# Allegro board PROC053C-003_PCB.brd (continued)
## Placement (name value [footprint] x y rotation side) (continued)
R468  DNI  [SM-7351-RES-0402]  106.68 108.92 270 bottom
R472  0  [SM-7351-RES-0603]  171.12 80.01 0 bottom
R473  0  [SM-7351-RES-0402]  156.46 73.53 0 bottom
R474  0  [SM-7351-RES-0402]  155.63 76.33 0 top
R475  0  [SM-7351-RES-0402]  159.56 71.51 90 top
R476  0  [SM-7351-RES-0402]  162.74 68.97 90 top
R477  0  [SM-7351-RES-0402]  163.63 71.51 90 top
R478  0  [SM-7351-RES-0402]  164.9 71.51 90 top
R479  12K  [SM-7351-RES-0402]  156.01 81.41 180 top
R480  0  [SM-7351-RES-0402]  160.71 71.51 90 top
R481  0  [SM-7351-RES-0402]  161.59 68.97 90 top
R482  0  [SM-7351-RES-0402]  165.91 71.51 90 top
R483  0  [SM-7351-RES-0402]  166.93 71.51 90 top
R484  4.7K  [SM-7351-RES-0402]  164.9 69.09 90 top
R485  10K  [SM-7351-RES-0402]  155.63 77.35 180 top
R486  0  [SM-7351-RES-0402]  113.03 62.74 270 top
R487  0  [SM-7351-RES-0402]  111.89 62.74 270 top
R489  0  [SM-7351-RES-0402]  169.09 71.51 90 top
R491  4.7K  [SM-7351-RES-0402]  163.12 88.78 90 top
R492  0  [SM-7351-RES-0402]  165.28 88.78 270 top
R493  220  [SM-7351-RES-0402]  161.98 88.78 90 top
R494  10K  [SM-7351-RES-0402]  164.13 88.78 270 top
R495  2.2K  [SM-7351-RES-0402]  162.61 85.98 270 bottom
R496  10K  [SM-7351-RES-0402]  163.63 85.98 90 bottom
R497  0  [SM-7351-RES-0402]  79.38 87.46 180 top
R498  DNI  [SM-7351-RES-0402]  61.21 64.14 270 bottom
R499  0  [SM-7351-RES-0402]  71.66 77.75 0 top
R500  DNI  [SM-7351-RES-0402]  62.36 64.14 270 bottom
R502  33  [SM-7351-RES-0402]  171.7 21.29 180 bottom
R503  120  [SM-7351-RES-0402]  155.58 11.13 90 bottom
R504  33  [SM-7351-RES-0402]  172.85 18.75 180 bottom
R505  49.9K  [SM-7351-RES-0402]  86.87 129.24 180 top
R506  49.9K  [SM-7351-RES-0402]  86.87 126.45 180 top
R507  49.9K  [SM-7351-RES-0402]  86.87 125.3 180 top
R508  49.9K  [SM-7351-RES-0402]  89.53 131.91 90 top
R509  49.9K  [SM-7351-RES-0402]  88.39 131.91 90 top
R510  49.9K  [SM-7351-RES-0402]  86.87 128.1 180 top
R511  49.9K  [SM-7351-RES-0402]  86.87 123.65 180 top
R512  49.9K  [SM-7351-RES-0402]  86.87 122.51 180 top
R513  49.9K  [SM-7351-RES-0402]  95.25 104.98 270 bottom
R514  0  [SM-7351-RES-0402]  16.13 13.92 180 bottom
R515  100K  [SM-7351-RES-0402]  16.13 16.21 0 bottom
R539  10K  [SM-7351-RES-0402]  53.72 38.23 270 top
R542  10K  [SM-7351-RES-0402]  49.53 38.23 270 top
R543  10K  [SM-7351-RES-0402]  50.67 38.23 270 top
R544  10K  [SM-7351-RES-0402]  52.58 38.23 270 top
R545  10K  [SM-7351-RES-0402]  54.86 38.23 90 top
R546  10K  [SM-7351-RES-0402]  33.91 34.63 0 bottom
R547  DNI  [SM-7351-RES-0402]  21.84 42.88 0 bottom
R548  10K  [SM-7351-RES-0402]  29.46 31.58 270 bottom
R549  10K  [SM-7351-RES-0402]  30.48 31.58 270 bottom
R550  0  [SM-7351-RES-0402]  30.73 31.58 270 top
R551  10K  [SM-7351-RES-0402]  23.88 14.22 180 bottom
R553  10K  [SM-7351-RES-0402]  24.38 3.17 270 bottom
R554  0  [SM-7351-RES-0402]  174.12 75.01 270 top
R555  0  [SM-7351-RES-0402]  175.13 75.01 270 top
R556  DNI  [SM-7351-RES-0402]  124.08 64.47 0 top
R557  DNI  [SM-7351-RES-0402]  85.47 90.51 0 top
R558  0  [SM-7351-RES-0402]  65.15 22.86 180 top
R559  0  [SM-7351-RES-0402]  65.15 23.88 0 top
R560  DNI  [SM-7351-RES-0402]  58.8 12.45 90 top
R561  DNI  [SM-7351-RES-0402]  56.52 12.45 270 top
R562  DNI  [SM-7351-RES-0402]  57.66 12.45 90 top
R563  DNI  [SM-7351-RES-0402]  127.89 66.88 0 top
R564  0  [SM-7351-RES-0402]  120.27 85.81 0 top
R565  0  [SM-7351-RES-0402]  127.89 86.82 180 top
R566  0  [SM-7351-RES-0402]  157.23 98.63 0 bottom
R567  0  [SM-7351-RES-0402]  157.23 97.62 0 bottom
R568  0  [SM-7351-RES-0402]  28.45 31.58 270 bottom
R569  0  [SM-7351-RES-0402]  81.91 84.28 180 bottom
R570  10K  [SM-7351-RES-0402]  143.51 130.76 0 bottom
R571  10K  [SM-7351-RES-0402]  147.83 114.76 270 top
R572  0  [SM-7351-RES-0402]  131.44 114.76 90 top
R573  0  [SM-7351-RES-0402]  106.68 8.25 270 top
R574  0  [SM-7351-RES-0402]  112.9 99.78 270 bottom
R575  0  [SM-7351-RES-0402]  112.9 103.84 270 top
R576  0  [SM-7351-RES-0402]  106.81 105.66 90 top
R577  100K  [SM-7351-RES-0402]  114.43 8.89 180 top
R578  100K  [SM-7351-RES-0402]  114.43 7.62 0 top
R579  2.2K  [SM-7351-RES-0402]  130.18 10.16 180 top
R580  100  [SM-7351-RES-0402]  60.2 37.21 0 top
R581  100  [SM-7351-RES-0402]  78.61 77.17 90 top
R582  0  [SM-7351-RES-0402]  120.27 65.99 180 top
R583  0  [SM-7351-RES-0402]  110.74 62.74 90 top
R584  0  [SM-7351-RES-0402]  92.46 102.19 270 top
R585  0  [SM-7351-RES-0402]  157.23 96.6 0 bottom
R586  0  [SM-7351-RES-0402]  143.76 96.22 180 bottom
R587  0  [SM-7351-RES-0402]  181.89 93.68 0 bottom
R588  0  [SM-7351-RES-0402]  132.72 114.68 90 bottom
R589  220  [SM-7351-RES-0402]  9.53 18.16 180 bottom
R590  0  [SM-7351-RES-0402]  9.53 17.1 0 bottom
R591  100K  [SM-7351-RES-0402]  9.53 16.08 0 bottom
R592  100K  [SM-7351-RES-0402]  16.13 19.64 0 bottom
R593  0  [SM-7351-RES-0402]  16.13 20.66 0 bottom
R594  0  [SM-7351-RES-0402]  9.53 20.53 0 bottom
R595  100K  [SM-7351-RES-0402]  9.53 19.51 0 bottom
R596  220  [SM-7351-RES-0402]  9.53 14.86 180 bottom
R597  100K  [SM-7351-RES-0402]  16.13 12.91 0 bottom
R598  0  [SM-7351-RES-0402]  16.13 17.23 0 bottom
R599  100K  [SM-7351-RES-0402]  9.53 12.78 0 bottom
R600  0  [SM-7351-RES-0402]  9.53 13.8 180 bottom
R601  220  [SM-7351-RES-0402]  9.53 21.59 180 bottom
R602  220  [SM-7351-RES-0402]  16.13 18.29 180 bottom
R603  220  [SM-7351-RES-0402]  16.13 21.72 180 bottom
R604  220  [SM-7351-RES-0402]  16.13 14.99 180 bottom
R605  0  [SM-7351-RES-0402]  127.89 94.57 180 top
R606  0  [SM-7351-RES-0402]  127.89 95.59 180 top
R607  0  [SM-7351-RES-0402]  131.44 101.17 0 top
R608  0  [SM-7351-RES-0402]  131.44 85.55 0 top
R609  0  [SM-7351-RES-0402]  131.44 88.98 0 top
R610  0  [SM-7351-RES-0402]  131.44 102.44 0 top
R611  0  [SM-7351-RES-0402]  131.44 98.13 0 top
R612  0  [SM-7351-RES-0402]  131.44 103.71 0 top
R613  0  [SM-7351-RES-0402]  127.89 92.2 0 top
R614  0  [SM-7351-RES-0402]  127.89 89.36 0 top
R615  0  [SM-7351-RES-0402]  131.44 92.79 0 top
R616  0  [SM-7351-RES-0402]  131.44 96.22 0 top
R617  0  [SM-7351-RES-0402]  124.08 96.35 0 top
R618  0  [SM-7351-RES-0402]  131.44 94.95 0 top
R619  0  [SM-7351-RES-0402]  131.44 99.4 0 top
R620  0  [SM-7351-RES-0402]  131.44 91.52 0 top
R621  0  [SM-7351-RES-0402]  124.08 95.08 0 top
R622  0  [SM-7351-RES-0402]  124.08 92.54 0 top
R623  0  [SM-7351-RES-0402]  124.08 91.27 0 top
R624  0  [SM-7351-RES-0402]  124.08 93.81 0 top
R625  0  [SM-7351-RES-0402]  131.44 86.82 0 top
R626  0  [SM-7351-RES-0402]  124.08 87.46 0 top
R627  0  [SM-7351-RES-0402]  124.08 88.73 0 top
R628  0  [SM-7351-RES-0402]  124.08 90 0 top
R630  100  [SM-7351-RES-0402]  78.61 122.13 270 bottom
R631  100  [SM-7351-RES-0402]  77.34 120.6 270 bottom
R632  100  [SM-7351-RES-0402]  77.34 123.65 90 bottom
R633  100  [SM-7351-RES-0402]  78.61 119.08 90 bottom
R634  0  [SM-7351-RES-0402]  120.27 87.08 180 top
R635  0  [SM-7351-RES-0402]  127.89 88.09 180 top
R636  0  [SM-7351-RES-0402]  124.08 86.31 180 top
R637  10K  [SM-7351-RES-0402]  157.23 99.65 180 bottom
R638  0  [SM-7351-RES-0402]  165.74 5.03 180 top
R639  0.05ohm  [SM_RES_LVK12]  64.26 75.39 90 top
R640  0.05ohm  [SM_RES_LVK12]  105.28 134.83 180 top
R641  0.01ohm  [SM_RES_LVK12]  112.65 134.7 180 top
R642  0.02ohm  [SM_RES_LVK12]  120.78 134.7 180 top
R643  0  [SM-7351-RES-0402]  74.93 73.66 0 top
R644  10K  [SM-7351-RES-0402]  86.61 107.4 90 top
R645  10K  [SM-7351-RES-0402]  93.85 103.25 90 top
R646  51K OHM  [RC0402]  157.39 117.9 90 top
R647  158K OHM  [RC0402]  161.07 121.58 90 top
R648  18.2K  [SM-7351-RES-0402]  161.07 119.42 90 top
R649  10K  [SM-7351-RES-0402]  45.59 38.23 90 top
R650  100  [SM-7351-RES-0402]  44.58 38.23 270 top
R652  0  [SM-7351-RES-0402]  50.29 24.64 270 top
R653  0  [SM-7351-RES-0402]  51.31 24.64 270 top
R654  10K  [SM-7351-RES-0402]  56.01 24.64 270 top
R655  100  [SM-7351-RES-0402]  54.99 24.64 90 top
R656  0  [SM-7351-RES-0603]  151.13 120.22 0 top
R657  0  [SM-7351-RES-0402]  137.01 128.34 0 bottom
R658  0  [SM-7351-RES-0402]  138.81 134.7 270 bottom
R659  0  [SM-7351-RES-0402]  85.47 89.49 0 top
R660  0  [SM-7351-RES-0402]  92.84 98.25 270 top
R661  0  [SM-7351-RES-0402]  119.63 74.25 180 bottom
R662  0  [SM-7351-RES-0402]  120.27 80.85 180 top
R663  0  [SM-7351-RES-0402]  105.54 113.37 270 top
R664  0  [SM-7351-RES-0402]  108.58 99.78 270 bottom
R665  0  [SM-7351-RES-0402]  104.52 113.37 270 top
R666  0  [SM-7351-RES-0402]  119.63 73.23 180 bottom
R669  0  [SM-7351-RES-0402]  113.54 99.78 90 top
R670  0  [SM-7351-RES-0402]  112.27 99.78 90 top
R671  0  [SM-7351-RES-0402]  111.38 99.78 90 bottom
R672  0  [SM-7351-RES-0402]  111.63 103.84 90 top
R673  0  [SM-7351-RES-0402]  127.89 85.81 180 top
R674  0  [SM-7351-RES-0402]  120.27 79.08 0 bottom
R675  0  [SM-7351-RES-0402]  127.89 83.27 180 top
R676  0  [SM-7351-RES-0402]  127.89 84.54 180 top
R677  0  [SM-7351-RES-0402]  179.1 80.73 180 bottom
R678  0  [SM-7351-RES-0402]  70.99 117.18 180 bottom
R679  0  [SM-7351-RES-0402]  158.78 117.9 270 top
R680  10K  [SM-7351-RES-0402]  73.53 114.89 270 bottom
R681  19.6K  [SM-7351-RES-0402]  73.53 112.86 90 bottom
R682  0  [SM-7351-RES-0402]  68.45 23.75 90 top
R683  0  [SM-7351-RES-0402]  69.47 23.75 90 top
R684  0  [SM-7351-RES-0402]  120.27 67.01 0 top
R685  0  [SM-7351-RES-0402]  124.08 68.28 180 top
R686  0  [SM-7351-RES-0402]  100.84 99.78 270 top
R687  100  [SM-7351-RES-0402]  77.34 117.68 90 bottom
R688  0  [SM-7351-RES-0402]  103.38 99.78 270 top
R689  0  [SM-7351-RES-0402]  104.27 121.75 270 top
R690  0  [SM-7351-RES-0402]  104.65 99.78 270 top
R691  0  [SM-7351-RES-0402]  105.92 99.78 270 top
R692  0  [SM-7351-RES-0402]  103.89 102.44 270 top
R693  220  [SM-7351-RES-0402]  72.64 105.54 180 bottom
R694  0  [SM-7351-RES-0402]  81.03 100.28 90 bottom
R695  100K  [SM-7351-RES-0402]  79.76 100.28 90 bottom
R696  220  [SM-7351-RES-0402]  76.07 105.54 180 bottom
R697  100K  [SM-7351-RES-0402]  76.45 100.28 90 bottom
R698  0  [SM-7351-RES-0402]  77.47 100.28 270 bottom
R699  220  [SM-7351-RES-0402]  79.5 105.54 180 bottom
R700  100K  [SM-7351-RES-0402]  72.9 100.28 90 bottom
R701  0  [SM-7351-RES-0402]  74.04 100.28 90 bottom
R702  220  [SM-7351-RES-0402]  68.83 103.5 180 bottom
R703  0  [SM-7351-RES-0402]  70.74 91.14 90 bottom
R704  100K  [SM-7351-RES-0402]  69.6 91.14 90 bottom
R705  220  [SM-7351-RES-0402]  69.22 89.41 180 bottom
R706  100K  [SM-7351-RES-0402]  69.47 84.03 90 bottom
R707  0  [SM-7351-RES-0402]  70.61 84.03 270 bottom
R708  220  [SM-7351-RES-0402]  67.18 95.12 180 bottom
R709  100K  [SM-7351-RES-0402]  69.09 98.25 90 bottom
R710  0  [SM-7351-RES-0402]  70.23 98.25 90 bottom
R711  DNI  [SM-7351-RES-0402]  132.46 101.17 180 top
R712  DNI  [SM-7351-RES-0402]  132.46 96.22 180 top
R713  DNI  [SM-7351-RES-0402]  125.09 93.81 180 top
R714  DNI  [SM-7351-RES-0402]  132.46 85.55 180 top
R715  DNI  [SM-7351-RES-0402]  132.46 88.98 180 top
R716  DNI  [SM-7351-RES-0402]  132.46 102.44 180 top
R717  DNI  [SM-7351-RES-0402]  132.46 103.71 180 top
R718  DNI  [SM-7351-RES-0402]  132.46 98.13 180 top
R719  DNI  [SM-7351-RES-0402]  132.46 92.79 180 top
R720  DNI  [SM-7351-RES-0402]  125.09 96.35 180 top
R721  DNI  [SM-7351-RES-0402]  132.46 99.4 180 top
R722  DNI  [SM-7351-RES-0402]  132.46 91.52 180 top
R723  DNI  [SM-7351-RES-0402]  132.46 94.95 180 top
R724  DNI  [SM-7351-RES-0402]  125.09 91.27 180 top
R725  DNI  [SM-7351-RES-0402]  132.46 86.82 180 top
R726  DNI  [SM-7351-RES-0402]  125.09 88.73 180 top
R727  DNI  [SM-7351-RES-0402]  125.09 90 180 top
R728  DNI  [SM-7351-RES-0402]  125.09 87.46 180 top
R729  100  [SM-7351-RES-0402]  161.54 7.96 90 top
R730  100  [SM-7351-RES-0402]  182.02 97.62 180 bottom
R731  100  [SM-7351-RES-0402]  184.68 95.2 90 bottom
R732  0  [SM-7351-RES-0402]  106.93 99.78 270 top
R733  0  [SM-7351-RES-0402]  106.05 102.44 270 top
R734  0  [SM-7351-RES-0402]  105.03 102.44 270 top
R735  0  [SM-7351-RES-0402]  107.06 102.44 90 top
R736  0  [SM-7351-RES-0402]  82.68 92.46 180 top
R737  0  [SM-7351-RES-0402]  82.68 91.44 180 top
R738  0  [SM-7351-RES-0402]  85.47 88.39 180 top
R739  0  [SM-7351-RES-0402]  131.06 59.31 270 top
R740  0  [SM-7351-RES-0402]  132.21 59.31 270 top
R741  10K  [SM-7351-RES-0402]  95 135.84 90 bottom
R742  0  [SM-7351-RES-0603]  140.34 126.07 270 bottom
R743  0  [SM-7351-RES-0402]  103.38 143.72 270 top
R744  0  [SM-7351-RES-0402]  120.9 99.9 270 top
R746  DNI  [SM-7351-RES-0402]  114.55 99.9 270 bottom
R747  DNI  [SM-7351-RES-0402]  118.36 97.74 90 bottom
R748  DNI  [SM-7351-RES-0402]  30.61 93.17 90 top
R749  DNI  [SM-7351-RES-0402]  119.51 101.17 90 bottom
R750  DNI  [SM-7351-RES-0402]  118.24 101.17 90 bottom
R751  DNI  [SM-7351-RES-0402]  114.55 101.94 90 bottom
R752  DNI  [SM-7351-RES-0402]  59.56 107.52 90 top
R753  DNI  [SM-7351-RES-0402]  52.58 107.52 90 top
R754  240  [SM-7351-RES-0402]  143.13 40.47 90 bottom
R755  240  [SM-7351-RES-0402]  143.13 55.71 90 bottom
R756  47  [SM-7351-RES-0402]  151 59.14 180 top
R757  47  [SM-7351-RES-0402]  144.02 70.95 270 bottom
R758  47  [SM-7351-RES-0402]  143 70.95 270 top
R759  47  [SM-7351-RES-0402]  151 66.25 180 top
R760  47  [SM-7351-RES-0402]  151 67.26 180 top
R761  47  [SM-7351-RES-0402]  151 65.23 180 top
R762  47  [SM-7351-RES-0402]  151 64.22 180 bottom
R763  47  [SM-7351-RES-0402]  151 61.17 180 top
R764  47  [SM-7351-RES-0402]  151 60.15 180 top
R765  47  [SM-7351-RES-0402]  146.05 70.95 270 bottom
R766  47  [SM-7351-RES-0402]  147.07 70.95 270 bottom
R767  47  [SM-7351-RES-0402]  148.08 70.95 270 bottom
R768  47  [SM-7351-RES-0402]  151 60.15 180 bottom
R769  47  [SM-7351-RES-0402]  151 66.25 180 bottom
R770  47  [SM-7351-RES-0402]  151 61.17 180 bottom
R771  47  [SM-7351-RES-0402]  151 62.18 180 top
R772  47  [SM-7351-RES-0402]  151 63.2 180 top
R773  47  [SM-7351-RES-0402]  151 63.2 180 bottom
R774  47  [SM-7351-RES-0402]  151 62.18 180 bottom
R775  47  [SM-7351-RES-0402]  151 65.23 180 bottom
R776  47  [SM-7351-RES-0402]  151 59.14 180 bottom
R777  47  [SM-7351-RES-0402]  145.03 70.95 270 bottom
R778  47  [SM-7351-RES-0402]  143 70.95 270 bottom
R779  47  [SM-7351-RES-0402]  151 64.22 180 top
R780  49.9  [SM-7351-RES-0402]  140.97 70.95 270 top
R781  49.9  [SM-7351-RES-0402]  141.99 70.95 270 top
R782  100K  [SM-7351-RES-0402]  163.45 57.1 0 bottom
R783  0  [SM-7351-RES-0402]  163.07 59.01 90 bottom
R784  10  [SM-7351-RES-0402]  157.23 60.66 90 bottom
R785  10K  [SM-7351-RES-0402]  160.66 54.18 90 bottom
R786  10K  [SM-7351-RES-0402]  159.51 54.18 270 bottom
R787  DNI  [SM-7351-RES-0402]  82.93 88.27 0 top
R788  100  [SM-7351-RES-0402]  8.76 44.32 0 bottom
R790  10K  [SM-7351-RES-0402]  16.89 42.88 90 top
R791  10K  [SM-7351-RES-0402]  18.41 46.82 180 top
R792  0  [SM-7351-RES-0402]  56.61 86.08 0 bottom
R793  20.5K  [SM-7351-RES-0402]  124.59 43.9 0 top
R794  0  [SM-7351-RES-0402]  140.69 122.38 270 bottom
R795  0  [SM-7351-RES-0402]  68.33 20.4 90 bottom
R796  0  [SM-7351-RES-0402]  65.66 23.07 90 bottom
R797  0  [SM-7351-RES-0402]  120.27 80.73 180 bottom
R798  10K  [SM-7351-RES-0402]  165.74 3.89 0 top
R799  10K  [SM-7351-RES-0402]  100.33 124.16 90 top
R800  10K  [SM-7351-RES-0402]  85.47 93.34 180 top
R801  0.05ohm  [SM_RES_LVK12]  65.53 53.8 0 top
R802  0  [SM-7351-RES-0402]  85.47 95.38 180 top
R803  0  [SM-7351-RES-0402]  85.47 91.52 180 top
R804  DNI  [SM-7351-RES-0402]  130.68 68.79 0 top
R805  DNI  [SM-7351-RES-0402]  130.68 70.31 0 top
R806  47  [SM-7351-RES-0402]  124.08 27.56 180 bottom
R807  47  [SM-7351-RES-0402]  144.91 55.71 90 bottom
R808  10K  [SM-7351-RES-0402]  8.76 43.18 0 bottom
R809  0  [SM-7351-RES-0402]  93.98 98.3 270 top
R810  10K  [SM-7351-RES-0402]  146.3 138.43 90 top
R811  10K  [SM-7351-RES-0402]  151.05 142.53 180 top
R812  1M  [SM-7351-RES-0402]  30.23 18.41 180 bottom
R813  1M  [SM-7351-RES-0402]  5.46 31.5 0 top
R814  10K  [SM-7351-RES-0402]  138.3 113.03 90 bottom
R854  0  [SM-7351-RES-0402]  145.67 125.98 270 bottom
R861  0  [SM-7351-RES-0402]  129.92 143 270 top
R862  0  [SM-7351-RES-0402]  133.22 143 270 top
R863  0  [SM-7351-RES-0402]  135.26 143 270 top
R864  0  [SM-7351-RES-0402]  137.29 143 270 top
R894  499  [SM-7351-RES-0402]  36.07 96.65 90 bottom
R895  10K  [SM-7351-RES-0402]  35.43 94.61 180 bottom
R896  DNI  [SM-7351-RES-0402]  34.92 96.65 90 bottom
R897  24.3K  [SM-7351-RES-0402]  38.1 91.31 180 bottom
R898  499  [SM-7351-RES-0402]  113.92 125.48 180 bottom
R899  10K  [SM-7351-RES-0402]  115.95 124.84 270 bottom
R900  DNI  [SM-7351-RES-0402]  113.92 124.33 180 bottom
R901  24.3K  [SM-7351-RES-0402]  119.25 127.51 270 bottom
R902  10K  [SM-7351-RES-0402]  164.85 149.1 270 bottom
R903  22.1  [SM-7351-RES-0402]  172.97 143 180 bottom
R905  DNI  [SM-7351-RES-0402]  163.83 146.56 180 bottom
R906  DNI  [SM-7351-RES-0402]  136.27 98.81 180 top
R907  DNI  [SM-7351-RES-0402]  137.03 90.93 180 top
R908  DNI  [SM-7351-RES-0402]  128.91 98.17 0 top
R909  DNI  [SM-7351-RES-0402]  127.89 91.19 0 top
R910  DNI  [SM-7351-RES-0402]  136.27 101.85 180 top
R911  DNI  [SM-7351-RES-0402]  129.29 103.76 0 top
R912  10K  [SM-7351-RES-0402]  124.08 25.02 180 top
R913  10K  [SM-7351-RES-0402]  149.61 70.48 180 top
R914  10K  [SM-7351-RES-0402]  165.99 52.45 180 bottom
R915  DNI  [SM-7351-RES-0402]  157.61 42.04 0 bottom
R916  100  [SM-7351-RES-0402]  170.05 42.93 0 bottom
R917  10K  [SM-7351-RES-0402]  166.24 46.1 90 bottom
R918  DNI  [SM-7351-RES-0402]  157.61 44.96 0 bottom
R919  DNI  [SM-7351-RES-0402]  157.61 46.74 0 bottom
R920  0  [SM-7351-RES-0402]  157.61 47.75 0 bottom
R921  0  [SM-7351-RES-0402]  157.61 41.02 0 bottom
R922  0  [SM-7351-RES-0402]  157.61 43.94 0 bottom
R923  0  [SM-7351-RES-0402]  66.93 79.63 180 top
R924  0  [SM-7351-RES-0402]  74.93 74.68 180 top
R925  0  [SM-7351-RES-0402]  66.93 81.41 180 top
R926  0  [SM-7351-RES-0402]  63.5 64.14 270 bottom
R927  DNI  [SM-7351-RES-0402]  79.88 89.15 270 top
R928  DNI  [SM-7351-RES-0402]  96.01 103.25 90 top
R929  DNI  [SM-7351-RES-0402]  95 103.25 270 top
R930  DNI  [SM-7351-RES-0402]  80.9 86.49 0 bottom
R931  0  [SM-7351-RES-0402]  80.9 85.34 0 bottom
R932  DNI  [SM-7351-RES-0402]  95 97.66 270 bottom
R933  0  [SM-7351-RES-0402]  92.08 97.66 270 bottom
R934  DNI  [SM-7351-RES-0402]  139.17 122.3 0 bottom
R935  0 OHM  [RC0402]  55.91 77.08 180 top
R938  1K OHM  [RC0402]  51.69 56.52 90 top
R939  10K  [SM-7351-RES-0402]  52.41 69.99 90 top
R940  0 OHM  [RC0402]  49.56 69.99 270 top
R941  10K  [SM-7351-RES-0402]  50.88 61.31 270 top
R942  10K  [SM-7351-RES-0402]  49.48 61.31 90 top
R943  DNI  [SM-7351-RES-0402]  47.03 61.02 270 top
R945  10K  [SM-7351-RES-0402]  45.38 61.38 0 top
R946  DNI  [SM-7351-RES-0402]  43.6 61.02 90 top
R947  10K  [SM-7351-RES-0402]  43.92 69.71 90 top
R948  10K  [SM-7351-RES-0402]  55.91 69.16 180 top
R950  DNI  [RC0402]  116.35 144.11 90 top
R951  DNI  [RC0402]  118.35 144.11 90 top
R952  DNI  [RC0402]  151.08 144.91 0 top
R953  DNI  [RC0402]  154.35 144.34 90 top
R954  10K  [SM-7351-RES-0402]  59.23 45.55 90 top
R955  10K  [SM-7351-RES-0402]  60.29 42.84 180 top
R956  DNI  [SM-7351-RES-0402]  7.7 105.74 270 bottom
R957  0  [SM-7351-RES-0402]  5.21 53.97 90 bottom
R958  DNI  [SM-7351-RES-0402]  5.21 56.6 90 bottom
R959  0 OHM  [RC0402]  47.37 56.52 90 top
R960  DNI  [RC0402]  45.95 56.52 90 top
R961  0 OHM  [RC0402]  44.48 56.52 90 top
R964  DNI  [RC0402]  45.44 69.71 90 top
R965  0 OHM  [RC0402]  50.22 56.52 90 top
R966  0 OHM  [RC0402]  48.79 56.52 90 top
R967  0 OHM  [RC0402]  51.07 69.99 90 top
R968  0 OHM  [RC0402]  55.94 75.86 180 top
R969  0 OHM  [RC0402]  55.94 74.26 180 top
R970  0 OHM  [RC0402]  55.91 72.59 180 top
R971  0 OHM  [RC0402]  55.66 78.68 180 top
R972  0 OHM  [RC0402]  55.66 80.13 180 top
R973  0 OHM  [RC0402]  55.91 70.92 180 top
R974  0 OHM  [RC0402]  44.23 72.25 0 top
R975  0 OHM  [RC0402]  44.23 73.78 0 top
R976  0 OHM  [RC0402]  44.23 75.3 0 top
R977  0 OHM  [RC0402]  44.23 76.83 0 top
R978  0 OHM  [RC0402]  44.23 78.35 0 top
R979  0 OHM  [RC0402]  44.23 79.87 0 top
R980  DNI  [RC0402]  46.77 69.71 90 top
R981  10K  [SM-7351-RES-0402]  148.93 140.95 90 top
R982  47K  [SM-7351-RES-0402]  155.26 140.82 0 top
R983  DNI  [SM-7351-RES-0402]  144.36 129.12 90 bottom
SCKT1  DNI  [SCK-SG-BGA-6334]  102.23 81.99 270 top
SW1  B3SL  [SW_B3SL-1022P]  166.88 44.15 180 top
SW2  B3SL  [SW_B3SL-1022P]  166.88 53.42 180 top
SW3  B3SL  [SW_B3SL-1022P]  166.88 62.44 180 top
TP1  TP  [TH_TP_5002]  175.92 129.88 0 top
TP1_1  TP  [TH_TP_5002]  177.72 14 90 top
TP2  TP1mm  [TP_SMD1MMCIRCLE]  137.54 109.56 0 top
TP3  TP1mm  [TP_SMD1MMCIRCLE]  137.54 107.27 0 top
TP6  TP1mm  [TP_SMD1MMCIRCLE]  139.32 107.27 0 top
TP7  TP1mm  [TP_SMD1MMCIRCLE]  131.95 107.7 0 top
TP8  TP  [TH_TP_5002]  80.26 149.86 0 top
TP9  TP  [TH_TP_5002]  187.86 120.6 0 top
TP10  TP  [TH_TP_5002]  75.22 2.67 0 top
TP11  TP  [TH_TP_5002]  2.67 14.1 0 top
TP16  TP1mm  [TP_SMD1MMCIRCLE]  43.56 119.84 0 top
TP17  TP1mm  [TP_SMD1MMCIRCLE]  63.25 120.1 0 top
TP18  TP1mm  [TP_SMD1MMCIRCLE]  172.77 76.71 0 top
TP19  TP1mm  [TP_SMD1MMCIRCLE]  69.09 79.63 0 top
TP20  TP1mm  [TP_SMD1MMCIRCLE]  51.69 40.51 0 top
TP21  TP1mm  [TP_SMD1MMCIRCLE]  148.08 138.26 0 top
TP22  TP1mm  [TP_SMD1MMCIRCLE]  126.49 78.06 0 top
TP23  TP1mm  [TP_SMD1MMCIRCLE]  128.4 78.06 0 top
TP24  TP1mm  [TP_SMD1MMCIRCLE]  158.55 95.38 0 top
TP25  TP  [TH_TP_5002]  151.89 136.26 0 top
U1  AM5729BABCXEA  [BGA23X23-760-117M]  102.23 81.62 270 top
U1_1  TLV70718  [X2SON1X1-4-16M]  174.99 8.9 270 top
U2  SN74LVC1G07  [U_5_DCK]  166.88 42.96 0 bottom
U3  TPS6590375ZWSR  [BGA12X12-169-55M]  139.45 125.94 0 top
U4  S25FL256S  [SOIC_16PIN_DW]  95.5 116.41 180 top
U5  MT41K256M16TW-107 AIT_P  [BGA96C80P9X16_800X1400X120]  85.98 31.88 0 top
U6  MT41K256M16TW-107 AIT_P  [BGA96C80P9X16_800X1400X120]  116.46 31.88 0 top
U7  MT41K256M16TW-107 AIT_P  [BGA96C80P9X16_800X1400X120]  101.22 31.88 0 top
U8  TPS51200  [DRCPSO_10PIN]  107.82 14.73 180 top
U9  TLK105L  [QFN5X5-32-39M]  21.34 118.7 0 bottom
U13  TLK105L  [QFN5X5-32-39M]  31.5 100.41 270 top
U15  TLK105L  [QFN5X5-32-39M]  31.5 82.63 270 top
U17  TLK105L  [QFN5X5-32-39M]  31.5 57.87 270 top
U18  PicoHaptics 304-100  [PICO_304-100]  140.84 17.65 180 top
U19  SN74LVC1G04  [SC70-5-43M]  187.22 85.81 90 bottom
U21  KSZ9031RN  [QFN7X7-48]  35.18 120.86 270 top
U22  SN74LVC1G07  [U_5_DCK]  35.81 110.06 270 bottom
U23  CDCE913  [TSSOP5X4-14-47M]  41.94 103.45 90 bottom
U24  KSZ9031RN  [QFN7X7-48]  56.9 120.86 270 top
U25  CDCE913  [TSSOP5X4-14-47M]  55.88 100.67 90 bottom
U26  SN74LVC1G07  [U_5_DCK]  57.53 110.06 270 bottom
U28  SN74LVC1G07  [U_5_DCK]  178.94 57.99 0 top
U30  TPD6E001  [U_10_RSE]  90.8 147.86 90 bottom
U32  TPS61081DRC  [U_10_DRC]  74.04 144.61 0 bottom
U33  CAT24C256W  [SOIC_8]  10.03 26.29 180 bottom
U34  SN74LVC1G00DCK  [U_5_DCK]  166.42 82.3 180 bottom
U35  SN74LVC1G07  [U_5_DCK]  159.89 75.06 90 bottom
U36  TPD2E001DRLR  [U_5_DRL]  182.27 14.1 180 top
U37  FT2232HL  [LQFP64PIN]  164.39 80.14 0 top
U38  93LC56B  [SOIC_8]  165.1 93.3 90 bottom
U39  DNI SN74LVC1G07  [U_5_DCK]  60.58 67.18 180 bottom
U40  R1Z-3.305HP  [SMD15X11-6-374M]  164.59 23.32 0 top
U41  ISO1050  [SO9X6-8-191M]  163.45 20.02 270 bottom
U43  MTFC16GAPALBH-IT  [BGA153N50P14X14_1150X1300X140]  95.63 126.7 270 bottom
U44  74LVC1G125  [SC70-5-43M]  56.9 40.64 270 top
U45  CDCM9102  [QFN5X5-32TI-39M]  29.59 36.4 180 bottom
U46  TPD12S016  [PW_24PIN_TSSOP]  64.64 18.16 180 top
U47  DNI SN74LVC1G07  [U_5_DCK]  125.48 46.23 90 top
U48  TPD1E10B06  [TPD1E10B06-2L]  170.31 53.55 0 bottom
U49  TPD1E10B06  [TPD1E10B06-2L]  170.56 41.18 270 bottom
U50  TPD1E10B06  [TPD1E10B06-2L]  160.91 60.41 180 top
U52  TPS76650  [SOIC_8]  97.79 10.41 90 bottom
U62  TPS63010  [U_20_DSBGA]  155.37 106.14 90 bottom
U63  SN74AVC4T245  [U_16_PW]  172.77 85.09 90 bottom
U64  TPD2EUSB30DRTR  [SOT1X1-3-20M]  43.05 19.43 270 top
U65  SN74AVC2T244  [SON2X1-8-16M]  173.99 71.68 90 top
U66  TPS2065D  [U_8_D]  26.29 8.89 180 bottom
U68  SN74LVC1G08  [SM-SO-SC70-5]  42.42 89.62 180 bottom
U69  SN74LVC1G08  [SM-SO-SC70-5]  31.12 90.12 180 bottom
U70  SN74LVC1G08  [SM-SO-SC70-5]  18.16 69.77 180 bottom
U71  SN74LVC1G08  [SM-SO-SC70-5]  26.16 46.82 180 bottom
U72  SN65HVS882  [U_28_PWP]  181.89 68.2 0 bottom
U73  TPIC2810  [U_16_D]  168.15 34.37 0 bottom
U74  ISO1176T  [U_16_DW]  122.3 8.25 90 top
U75  SN74AVC2T244  [SON2X1-8-16M]  171.04 65.11 90 bottom
U76  TPS71712  [SMDSC70-5]  147.57 100.16 270 top
U77  SN65HVD78D  [SOIC_8]  177.17 8.84 0 bottom
U78  SN74LVC1G07  [SC70-5-43M]  187.1 94.19 90 bottom
U79  TPS61085  [MSOP3X3-8-43M]  158.4 122.59 90 top
U80  TPD1E10B06  [TPD1E10B06-2L]  92.2 8.51 180 top
U81  TPD1E10B06  [TPD1E10B06-2L]  94.61 8.51 0 top
U82  TPD1E10B06  [TPD1E10B06-2L]  160.78 11.43 180 top
U83  TPD1E10B06  [TPD1E10B06-2L]  163.2 11.43 0 top
U84  TPD1E10B06  [TPD1E10B06-2L]  96.99 134.13 0 top
U85  SN74LVC1G08  [SM-SO-SC70-5]  56.87 46.2 180 top
U86  LP38693ADJ  [SOT-223-5]  68.33 112.86 180 bottom
U87  TPD1E10B06  [TPD1E10B06-2L]  158.37 13.34 0 bottom
U88  TPD1E10B06  [TPD1E10B06-2L]  156.21 13.34 180 bottom
U89  TC358778  [BGA7X7-80-39M]  150.5 95.97 90 bottom
U90  MT41K256M16TW-107 AIT_P  [BGA96C80P9X16_800X1400X120]  140.84 48.09 270 bottom
U91  MT41K256M16TW-107 AIT_P  [BGA96C80P9X16_800X1400X120]  140.84 63.33 270 bottom
U92  TPS51200  [DRCPSO_10PIN]  159.89 57.49 90 bottom
U93  TPD4S012  [U_6_DRY]  6.6 40.59 270 top
U94  TPS2051BD  [U_8_D]  20.83 41.99 180 top
U95  TPD4E05U06  [USON2X1-10-22M]  39.75 19.05 90 bottom
U96  SN74LVC1G07  [SC70-5-43M]  147.98 143.18 0 top
U97  SN74LVC1G07  [U_5_DCK]  164.34 50.04 90 bottom
U98  SN74LVC1G08  [SM-SO-SC70-5]  163.58 43.94 0 bottom
U99  SN74CBTLV3257PWR  [SOP65P640X120-16N]  50.22 75.47 180 top
U101  SN74LVC139APWR  [SOP65P640X120-16N]  47.51 50.13 270 top
U102  SN74AUP2G125DCUR  [SOP50P310X90-8]  50.26 65.59 270 top
U103  SN74AUP2G125DCUR  [SOP50P310X90-8]  44.62 65.3 270 top
U104  TPS3808G33DBVR  [SOT-23-6]  152 139.49 0 top
X1  20.000 MHZ  [OSC7X5-71M]  169.93 147.57 0 bottom
Y1  20.000MHz  [XTAL_ABM7]  73.54 81.64 270 top
Y2  16.384MHz  [XTAL3225-39M]  136.27 138 180 top
Y3  25MHz  [SM_OSC_ABM3]  49.18 103.19 270 bottom
Y4  25MHz  [SM_OSC_ABM3]  62.86 99.65 270 bottom
Y5  12MHz  [SM_OSC_ABM3]  151.43 84.33 270 top
Y6  32.768KHz MC-306  [MC-306]  72.26 88.09 180 top
Y7  25MHz  [ASF_SMD3_2X5MM]  21.72 40.21 270 bottom

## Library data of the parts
C1 C2 = 04025A180JAT2A
C1_1 C2_1 C23 C316 C421 C459 = CL10A105KB8NNNC
C3 C7-C12 C14-C17 C28-C32 C34-C43 C48-C51 C55-C63 C65-C79 C81 C105 C112-C115 C118 C120 C127 C130 C137 C139 C142 C144 C151 C152 C165 C169-C171 C186 C190-C192 C195 C207 C210 C214 C216 C219-C221 C225-C230 C232-C236 C238-C240 C242 C248 C251 C255-C258 C261-C264 C267 C308-C310 C315 C319 C321 C322 C324 C326-C332 C334-C339 C341-C346 C348 C349 C351-C353 C355-C360 C362-C365 C367-C374 C376-C381 C385 C386 C388 C389 C391 C394 C400 C401 C403-C406 C408-C410 C420 C422-C430 C443 C444 C448 C451 C453 C469 C470 C480-C482 C485-C491 C493-C502 C506-C509 C511-C520 C524 C547 C548 C550-C553 C564 C567 C569 C571-C577 = CC0402KRX7R7BB103
C4 C5 C209 C265 C286-C300 C350 C407 C442 C445-C447 C484 C565 C568 = CGB2A1X5R1E105K033BC
C6 C13 C22 C88 C91 C92 C95-C97 C110 C125 C136 C149 C154 C156 C159 C161 C163 C168 C175 C177 C180 C182 C184 C189 C215 C222 C266 C305-C307 C317 C320 C333 C340 C347 C354 C361 C375 C384 C387 C395 C396 C413 C414 C433 C458 C483 C532 C534-C536 C540 C541 = CL21A106KOQNNNG
C20 C21 C44-C47 C53 C54 C80 C82 C83 C85 C87 C89 C90 C93 C94 C98-C100 C102-C104 C107-C109 C111 C116 C117 C119 C122-C124 C126 C128 C129 C132-C135 C138 C140 C141 C143 C145 C147 C148 C150 C153 C155 C160 C162 C164 C174 C176 C181 C183 C185 C211 C213 C245 C252 C313 C314 C390 C393 C415 C417 C436-C439 C454-C457 C460 C477 C478 C503-C505 C521-C523 C525-C531 C537-C539 C542 C549 C557 C559 C563 C566 = CC0402JRX7R7BB104
C24 C411 C412 C440 C441 = 1C_100uFCapacitor16V20%ElecPoly
C25 C26 = C0402C270J5GACTU: Tolerance: TOLERANCE
C27 C166 C167 C187 C188 C303 C304 C431 C432 C434 C449 C556 = CGA2B3X7R1H104K050BE
C33 C52 C64 C418 C419 C492 C510 = CL21A226MOCLRNC
C84 C86 C196 C543 C544 C558 C560 = 1C_0.001uFCapacitor50V5%0402: User Part Number: USERPART#; Tolerance: TOLERANCE
C101 C533 = 1C_10pFCapacitor50V1%smd0402: User Part Number: USERPART#; Tolerance: TOLERANCE
C106 C121 C131 C146 = 04025C472KAT2A
C157 C158 C178 C179 C268-C271 C276-C280 C579 = CL31A476MPHNNNE
C172 C173 C193 C194 C243 C244 = CL05C180JB5NNNC
C197-C204 = C0402C223K5RACAUTO
C205 C208 C224 C464-C468 C471 C472 C479 C578 = 1C_2.2uF16V10%SMD0805
C206 C435 = GRT31CR61H106KE01L
C212 C217 C231 C237 C241 C272-C275 C281-C285 C416 C546 = 1C_4.7uFCapacitor16V10%0603
C218 = GRT21BR61H475ME13L
C223 C570 C580 = C0402C104J4RACTU: Tolerance: TOLERANCE
C246 C247 = CC0402JRNPO9BN150
C249 C250 = C1608JB1C335K080AC
C253 C254 = C0402C101J3GACTU
C301 C302 C318 C382 C383 C392 C399 C402 C562 = C1005X5R0J225M050BC
C311 C545 = T495D157K010ATE100
C323 C325 = 4.7uFCapacitor16V20%Tant
C450 C452 = 1C_10uFCapacitor6.3V20%0603
C461 C462 = GRM21BR6YA106KE43L
C463 = 1C_1.1nFCapacitor50V5%0603
C473-C475 = T491D476K010AT
C476 = 1C_2.2uFCapacitor10V20%smd0402: User Part Number: USERPART#; Tolerance: TOLERANCE
C554 C555 = CC0402JRX7R7BB104: signal model: 1C_0.1UFCAPACITOR16V10%0402_SM-_0.1uF
D1 = 1E_Diode_15ARect_rev45V
D2 = SMCJ5.0A
D3 D4 = Diode200mA250V_0
D5-D13 = 5988170107F
D14 D15 = MBR0520LT1G
D16-D19 D22 D23 = SM1210RGB
D20 = PMEG2010BELD,315
D24 D25 = TLVH431_0
F1 = 1P_Fuse_0
FB1-FB8 = BLM18BB100SN1D
FB9-FB11 = MPZ1608S221ATA00
FB12 FB13 FB19 = 1L_FerBead_0
J1 = 2J_Conn_PwrJack_RAPC712
J1_1 = 2H_Header_4x1_female
J2 = 2C_Conn_LeadScrewDown_2pin
J3 J5 J6 J8 = 2J_ConnectorRJ45_10_0
J4 J7 J38 = 2H_Header_5x1
J9 = 2H_Header12x2
J10 J12 = 2J_ConnectorRJ45_Gigabit
J14 = 2C_Conn_DSUB9F
J15 = 503182-1852_CUS
J16 = 2C_Conn_FFC_0.5mm_32pos
J17 = XF2M-0615-1A
J18 = 2C_Conn_JTAGMIPI_60pin
J19 J45 = USB
J21 = NPPN302AFCN-RC
J22 = 2C_PCIEConnector_10018783
J23 = 1932258-1
J24 = 2C_Conn_HDMI_TypeA
J37 = 2H_Header15x2_0.1in_Female
J39 = 2H_Header_3x1
J40-J44 J47 J49-J51 = 2H_Header_0
J46 = 2H_Header_4x1
L1 = 1L_0.7Asmd
L2 = DA2304-ALB
L3 L21 L24-L26 L34 L35 = 1L_NFM21PC474_EMIFilter_0
L11 L33 = ACM2012H-900-2P-T05
L12-L20 = SRP4012TA-1R0M
L22 = SRN5040-4R7M
L28 = 1L_0.5Asmd
L29-L32 = 1M_DLW21SN900HQ2L_0: signal model: 1M_DLW21SN900HQ2L_DLW21SN900HQ2_DLW21SN900HQ2L
Q1-Q6 Q9-Q16 Q20-Q25 = 1Q_MOSFET_NChan_BSS138_0
Q7 Q8 = NTF6P02T3G
Q26 Q27 = 1Q_MOSFET_PChan_FDT434P_0
R1_1 R97 R138 R141 R180 R218 R222 R278 R322 R472 R656 R742 = 1R_ZeroOhmResistor1/16W0603
R2 R2_1 R10 R18 R22 R32-R35 R37-R40 R45 R48 R107 R149 R153 R190 R233 R259 R299 R301 R306 R309 R343 R345 R352 R353 R364 R366 R397-R401 R412 R417 R420 R421 R425 R430-R432 R453-R468 R485 R494 R496 R498 R539 R542-R546 R548 R549 R551 R553 R561 R570 R571 R637 R644 R645 R649 R654 R741 R785 R786 R790 R791 R798-R800 R804 R805 R808 R810 R811 R814 R895 R896 R899 R900 R902 R912-R914 R917 R939 R941-R943 R945-R948 R954 R955 R981 R983 = RMCF0402FT10K0
R3 R281-R292 R325-R336 R426 = RMCF0402FT22R1: signal model: 1R_22OHMRESISTOR1/16W1%0402_SM-_22
R4 R305 R349 = 1MOhmResistor1/16W0402
R5-R9 R13-R15 R19 R20 R29 R67 R77 R78 R89 R93 R105 R106 R112 R114 R115 R117-R119 R121 R122 R134 R148 R150 R151 R154 R160 R161 R172 R176 R188 R189 R195-R199 R202 R203 R214 R230 R231 R234 R241 R243 R247 R248 R253 R254 R273-R275 R277 R294 R295 R300 R308 R312 R314 R338 R339 R351 R356 R358 R367 R369 R371 R377 R380 R381 R385 R387 R393 R394 R409-R411 R416 R418 R428 R451 R473-R478 R480-R483 R486 R487 R489 R492 R497 R499 R500 R514 R547 R550 R554 R555 R557-R559 R564 R566-R569 R572-R576 R582-R588 R590 R593 R594 R598 R600 R638 R643 R652 R653 R657-R666 R669-R679 R682-R686 R688-R692 R694 R698 R701 R703 R707 R710 R732-R740 R743 R744 R746-R753 R783 R787 R792 R794-R797 R802 R803 R809 R854 R861-R864 R905-R911 R915 R918-R927 R930-R934 R957 = 1R_ZeroOhmResistor1/16W0402
R11 R429 R580 R581 R630-R633 R650 R655 R687 R788 R916 = 1R_100ohm1/16W1%SMD0402
R16 R17 R21 R304 R317 R319 R321 R348 R361 R363 = 1R_1KOhmResistor1/16W0402
R23-R28 R30 R31 R79-R88 R90-R92 R94-R96 R98 R123-R130 R132 R133 R135-R137 R139 R140 R142 R162-R171 R173-R175 R177 R179 R181 R204-R213 R215-R217 R219-R221 R223 R257 R258 R260-R265 R267 R269 R271 R402-R407 R565 R605-R628 R634-R636 R711-R728 = 1R_ZeroOhmResistor1/16W0402: signal model: 1R_ZEROOHMRESISTOR1/16W0402_SM-_0
R36 R648 R929 = 1R_18.2Kohm1/16W1%smd0402
R41 R42 R44 R754 R755 = 1R_240OhmResistor1/16W0402
R46 R47 R99-R102 R143-R146 R182-R185 R224-R227 R780 R781 R958 = 1R_49.9OhmResistor1/16W0402
R49-R55 R57-R66 R68 R70-R75 R756-R779 R806 R807 = 1R_47ohm1/16W1%smd0402
R56 R245 R246 R251 R252 R255 R256 R280 R324 R419 R515 R577 R578 R591 R592 R595 R597 R599 R695 R697 R700 R704 R706 R709 R782 = 1R_100KOhmResistor1/16W0402
R69 R413 R784 = 1R_10ohm1/16W5%smd0402
R76 R104 R108-R111 R116 R120 R131 R152 R155-R159 R187 R191-R194 R200 R201 R232 R235-R238 R383 R384 R495 R556 R563 R579 R956 = 1R_2.2KOhmResistor1/16W0402
R103 R147 R186 R228 = 1R_4.87Kohm1/16W1%smd0402
R113 = RMCF0402FT62R0
R239 R240 R242 R244 R249 R250 R386 R388-R392 R395 R396 R589 R596 R601-R604 R693 R696 R699 R702 R705 R708 = 1R_150ohm1/16W1%SMD0402
R276 R903 = RMCF0402FT22R1
R279 = RC0402JR-071K5L
R293 R296 R337 R340 R493 = 1R_220ohm1/10W1%smd0402
R297 R342 R422 R423 R433 R450 R484 R491 R560 R562 = 1R_4.7KOhmResistor1/16W0402
R298 R341 = 1R_12.1KohmResistor1/16W1%0402
R310 R313 R315 R354 R357 R359 R502 R504 = 1R_33ohmResistor1/16W5%0402
R368 R370 R372-R376 R378 = ERJ-6ENF1201V
R379 = ERJ-6ENF49R9V
R382 = 1R_25Kohm1/10W0.1%smd0603
R408 = 470Kohm1/16W1%SMD0402
R414 R982 = 1R_47KOhmResistor1/16W0402
R415 = 1R_2OhmResistor1/10W1%0603
R424 = 1R_1.62MOhmResistor1/16W0402
R427 = 1R_180KOhmResistor1/16W0402
R434-R449 = 1R_18KohmResistor1/10W1%smd0402
R479 = 1R_12Kohm1/16W1%SMD0402
R503 = 1R_120ohm1/16W1%smd0402
R505-R513 = 1R_49.9KOhmResistor1/16W0402
R639 R640 R801 = LVK12R050DER
R641 = LVK12R010DER
R642 = LVK12R020FER
R646 = RC0402FR-0751KL
R647 = RC0402FR-07158KL
R680 = 1R_10KOhmResistor1/10W1%0402
R681 = 1R_19.6KohmResistor1/16W1%0402
R729-R731 = 1R_100ohm1/10W1%SMD0402
R793 R928 = 1R_20.5Kohm1/16W1%smd0402
R812 R813 = 1R_1MOhmResistor1/16W0402
R894 R898 = RMCF0402FT499R
R897 R901 = RMCF0402FT24K3
R935 R940 R950-R953 R959-R961 R964-R980 = ERJ-2GE0R00X
R938 = ERJ-2GEJ102X
SCKT1 = AM57XX_SOCKET
SW1-SW3 = 2W_Switch_Pushbuttonsmd
TP1 TP1_1 TP8-TP11 TP25 = 2H_TestPointThroughHole
TP2 TP3 TP6 TP7 TP16-TP24 = 2H_Testpoint_SMD1mmCircle
U1 = AM5729BABCXEA
U1_1 = 1A_TLV70717
U2 U22 U26 U28 U35 U39 U47 U78 U96 U97 = SN74LVC1G07DCKRE4
U3 = TPS6590379ZWSR
U4 = 1A_S25FL256S_QSPI
U5-U7 U90 U91 = MT41K256M16TW-107 AIT_P
U8 U92 = TPS51200DRCT
U9 U13 U15 U17 = TLK105LRHBR
U18 = 1G_Haptics_Pico_0
U19 = SN74LVC1G04DCKRE4
U21 U24 = KSZ9031RNXCC
U23 U25 = 1A_CDCE913
U30 = TPD6E001RSER
U32 = TPS61081DRCT
U33 = 1A_CAT24C256W
U34 = SN74LVC1G00DCKR
U36 = TPD2E001DRLR
U37 = 1A_FT2232_2
U38 = 1A_93C56EEPROM2Kbit
U40 = 1A_IsoReg5V_R1Z-3.305HP
U41 = 1A_ISO1050
U43 = MTFC16GAPALBH-IT
U44 = SN74LVC1G125DCKR
U45 = CDCM9102RHBT
U46 = TPD12S016PWR
U48-U50 U80-U84 U87 U88 = TPD1E10B06DPYR
U52 = TPS76650
U62 = TPS63010YFFR
U63 = 1A_SN74AVC4T245
U64 = TPD2EUSB30DRTR
U65 U75 = SN74AVC2T244DQMR
U66 = 1A_TPS2065D
U68-U71 U85 U98 = SN74LVC1G08DCKR
U72 = 1A_SN65HVS882
U73 = 1A_TPIC2810
U74 = 1A_ISO1176T
U76 = TPS71712DCKR
U77 = 1A_SN65HVD78
U79 = TPS61085DGKT
U86 = LP38693MP-ADJ/NOPB
U89 = 1A_TC358778XBG
U93 = TPD4S012DRYR
U94 = 1A_TPS2051BD
U95 = TPD4E05U06DQAR
U99 = SN74CBTLV3257PWR
U101 = SN74LVC139APWR
U102 U103 = SN74AUP2G125DCUR
U104 = TPS3808G33DBVR
X1 = CB3LV-3C-20M0000
Y1 = ABM7-20.000MHZ-D2Y-T
Y2 = 1Y_Crystal16.384MHz
Y3 Y4 = 1Y_Crystal25MHzABM3_0
Y5 = 1Y_Crystal12MHzABM3_0
Y6 = MC-306 32.7680K-A0
Y7 = 1Y_Oscillator25MHzSMD

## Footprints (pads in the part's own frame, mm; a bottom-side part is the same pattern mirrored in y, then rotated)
ACM2012H
  rect 0.75x0.4 smd: 1(-0.925,0.4) 2(-0.925,-0.4) 3(0.925,-0.4) 4(0.925,0.4)
ASF_SMD3_2X5MM
  rect 1.5x1.7 smd: 1(-1.1,1.27) 2(-1.1,-1.27) 3(1.1,-1.27) 4(1.1,1.27)
BGA7X7-80-39M
  round 0.25 smd: A1(-2.925,2.925) A2(-2.275,2.925) A3(-1.625,2.925) A4(-0.975,2.925) A5(-0.325,2.925) A6(0.325,2.925) A7(0.975,2.925) A8(1.625,2.925) A9(2.275,2.925) A10(2.925,2.925) B1(-2.925,2.275) B2(-2.275,2.275) B3(-1.625,2.275) B4(-0.975,2.275) B5(-0.325,2.275) B6(0.325,2.275) B7(0.975,2.275) B8(1.625,2.275) B9(2.275,2.275) B10(2.925,2.275) C1(-2.925,1.625) C2(-2.275,1.625) C9(2.275,1.625) C10(2.925,1.625) D1(-2.925,0.975) D2(-2.275,0.975) D4(-0.975,0.975) D5(-0.325,0.975) D6(0.325,0.975) D7(0.975,0.975) D9(2.275,0.975) D10(2.925,0.975) E1(-2.925,0.325) E2(-2.275,0.325) E4(-0.975,0.325) E5(-0.325,0.325) E6(0.325,0.325) E7(0.975,0.325) E9(2.275,0.325) E10(2.925,0.325) F1(-2.925,-0.325) F2(-2.275,-0.325) F4(-0.975,-0.325) F5(-0.325,-0.325) F6(0.325,-0.325) F7(0.975,-0.325) F9(2.275,-0.325) F10(2.925,-0.325) G1(-2.925,-0.975) G2(-2.275,-0.975) G4(-0.975,-0.975) G5(-0.325,-0.975) G6(0.325,-0.975) G7(0.975,-0.975) G9(2.275,-0.975) G10(2.925,-0.975) H1(-2.925,-1.625) H2(-2.275,-1.625) H9(2.275,-1.625) H10(2.925,-1.625) J1(-2.925,-2.275) J2(-2.275,-2.275) J3(-1.625,-2.275) J4(-0.975,-2.275) J5(-0.325,-2.275) J6(0.325,-2.275) J7(0.975,-2.275) J8(1.625,-2.275) J9(2.275,-2.275) J10(2.925,-2.275) K1(-2.925,-2.925) K2(-2.275,-2.925) K3(-1.625,-2.925) K4(-0.975,-2.925) K5(-0.325,-2.925) K6(0.325,-2.925) K7(0.975,-2.925) K8(1.625,-2.925) K9(2.275,-2.925) K10(2.925,-2.925)
BGA12X12-169-55M
  round 0.4 smd: A1(-4.8,4.8) A2(-4,4.8) A3(-3.2,4.8) A4(-2.4,4.8) A5(-1.6,4.8) A6(-0.8,4.8) A7(0,4.8) A8(0.8,4.8) A9(1.6,4.8) A10(2.4,4.8) A11(3.2,4.8) A12(4,4.8) A13(4.8,4.8) B1(-4.8,4) B2(-4,4) B3(-3.2,4) B4(-2.4,4) B5(-1.6,4) B6(-0.8,4) B7(0,4) B8(0.8,4) B9(1.6,4) B10(2.4,4) B11(3.2,4) B12(4,4) B13(4.8,4) C1(-4.8,3.2) C2(-4,3.2) C3(-3.2,3.2) C4(-2.4,3.2) C5(-1.6,3.2) C6(-0.8,3.2) C7(0,3.2) C8(0.8,3.2) C9(1.6,3.2) C10(2.4,3.2) C11(3.2,3.2) C12(4,3.2) C13(4.8,3.2) D1(-4.8,2.4) D2(-4,2.4) D3(-3.2,2.4) D4(-2.4,2.4) D5(-1.6,2.4) D6(-0.8,2.4) D7(0,2.4) D8(0.8,2.4) D9(1.6,2.4) D10(2.4,2.4) D11(3.2,2.4) D12(4,2.4) D13(4.8,2.4) E1(-4.8,1.6) E2(-4,1.6) E3(-3.2,1.6) E4(-2.4,1.6) E5(-1.6,1.6) E6(-0.8,1.6) E7(0,1.6) E8(0.8,1.6) E9(1.6,1.6) E10(2.4,1.6) E11(3.2,1.6) E12(4,1.6) E13(4.8,1.6) F1(-4.8,0.8) F2(-4,0.8) F3(-3.2,0.8) F4(-2.4,0.8) F5(-1.6,0.8) F6(-0.8,0.8) F7(0,0.8) F8(0.8,0.8) F9(1.6,0.8) F10(2.4,0.8) F11(3.2,0.8) F12(4,0.8) F13(4.8,0.8) G1(-4.8,0) G2(-4,0) G3(-3.2,0) G4(-2.4,0) G5(-1.6,0) G6(-0.8,0) G7(0,0) G8(0.8,0) G9(1.6,0) G10(2.4,0) G11(3.2,0) G12(4,0) G13(4.8,0) H1(-4.8,-0.8) H2(-4,-0.8) H3(-3.2,-0.8) H4(-2.4,-0.8) H5(-1.6,-0.8) H6(-0.8,-0.8) H7(0,-0.8) H8(0.8,-0.8) H9(1.6,-0.8) H10(2.4,-0.8) H11(3.2,-0.8) H12(4,-0.8) H13(4.8,-0.8) J1(-4.8,-1.6) J2(-4,-1.6) J3(-3.2,-1.6) J4(-2.4,-1.6) J5(-1.6,-1.6) J6(-0.8,-1.6) J7(0,-1.6) J8(0.8,-1.6) J9(1.6,-1.6) J10(2.4,-1.6) J11(3.2,-1.6) J12(4,-1.6) J13(4.8,-1.6) K1(-4.8,-2.4) K2(-4,-2.4) K3(-3.2,-2.4) K4(-2.4,-2.4) K5(-1.6,-2.4) K6(-0.8,-2.4) K7(0,-2.4) K8(0.8,-2.4) K9(1.6,-2.4) K10(2.4,-2.4) K11(3.2,-2.4) K12(4,-2.4) K13(4.8,-2.4) L1(-4.8,-3.2) L2(-4,-3.2) L3(-3.2,-3.2) L4(-2.4,-3.2) L5(-1.6,-3.2) L6(-0.8,-3.2) L7(0,-3.2) L8(0.8,-3.2) L9(1.6,-3.2) L10(2.4,-3.2) L11(3.2,-3.2) L12(4,-3.2) L13(4.8,-3.2) M1(-4.8,-4) M2(-4,-4) M3(-3.2,-4) M4(-2.4,-4) M5(-1.6,-4) M6(-0.8,-4) M7(0,-4) M8(0.8,-4) M9(1.6,-4) M10(2.4,-4) M11(3.2,-4) M12(4,-4) M13(4.8,-4) N1(-4.8,-4.8) N2(-4,-4.8) N3(-3.2,-4.8) N4(-2.4,-4.8) N5(-1.6,-4.8) N6(-0.8,-4.8) N7(0,-4.8) N8(0.8,-4.8) N9(1.6,-4.8) N10(2.4,-4.8) N11(3.2,-4.8) N12(4,-4.8) N13(4.8,-4.8)
BGA23X23-760-117M
  round 0.4 smd: A1(-10.8,10.8) A2(-10,10.8) A3(-9.2,10.8) A4(-8.4,10.8) A5(-7.6,10.8) A6(-6.8,10.8) A7(-6,10.8) A8(-5.2,10.8) A9(-4.4,10.8) A10(-3.6,10.8) A11(-2.8,10.8) A12(-2,10.8) A13(-1.2,10.8) A14(-0.4,10.8) A15(0.4,10.8) A16(1.2,10.8) A17(2,10.8) A18(2.8,10.8) A19(3.6,10.8) A20(4.4,10.8) A21(5.2,10.8) A22(6,10.8) A23(6.8,10.8) A24(7.6,10.8) A25(8.4,10.8) A26(9.2,10.8) A27(10,10.8) A28(10.8,10.8) AA1(-10.8,-5.2) AA2(-10,-5.2) AA3(-9.2,-5.2) AA4(-8.4,-5.2) AA5(-7.6,-5.2) AA6(-6.8,-5.2) AA7(-6,-5.2) AA8(-5.2,-5.2) AA9(-4.4,-5.2) AA10(-3.6,-5.2) AA11(-2.8,-5.2) AA12(-2,-5.2) AA13(-1.2,-5.2) AA14(-0.4,-5.2) AA15(0.4,-5.2) AA16(1.2,-5.2) AA17(2,-5.2) AA18(2.8,-5.2) AA19(3.6,-5.2) AA20(4.4,-5.2) AA21(5.2,-5.2) AA22(6,-5.2) AA23(6.8,-5.2) AA24(7.6,-5.2) AA25(8.4,-5.2) AA26(9.2,-5.2) AA27(10,-5.2) AA28(10.8,-5.2) AB1(-10.8,-6) AB2(-10,-6) AB3(-9.2,-6) AB4(-8.4,-6) AB5(-7.6,-6) AB6(-6.8,-6) AB7(-6,-6) AB8(-5.2,-6) AB9(-4.4,-6) AB10(-3.6,-6) AB11(-2.8,-6) AB12(-2,-6) AB13(-1.2,-6) AB14(-0.4,-6) AB15(0.4,-6) AB16(1.2,-6) AB17(2,-6) AB18(2.8,-6) AB19(3.6,-6) AB20(4.4,-6) AB21(5.2,-6) AB22(6,-6) AB23(6.8,-6) AB24(7.6,-6) AB25(8.4,-6) AB27(10,-6) AB28(10.8,-6) AC1(-10.8,-6.8) AC2(-10,-6.8) AC3(-9.2,-6.8) AC4(-8.4,-6.8) AC5(-7.6,-6.8) AC6(-6.8,-6.8) AC7(-6,-6.8) AC8(-5.2,-6.8) AC9(-4.4,-6.8) AC10(-3.6,-6.8) AC11(-2.8,-6.8) AC12(-2,-6.8) AC13(-1.2,-6.8) AC14(-0.4,-6.8) AC15(0.4,-6.8) AC16(1.2,-6.8) AC17(2,-6.8) AC18(2.8,-6.8) AC19(3.6,-6.8) AC20(4.4,-6.8) AC21(5.2,-6.8) AC22(6,-6.8) AC23(6.8,-6.8) AC24(7.6,-6.8) AC25(8.4,-6.8) AC26(9.2,-6.8) AC27(10,-6.8) AC28(10.8,-6.8) AD1(-10.8,-7.6) AD2(-10,-7.6) AD3(-9.2,-7.6) AD4(-8.4,-7.6) AD5(-7.6,-7.6) AD6(-6.8,-7.6) AD7(-6,-7.6) AD8(-5.2,-7.6) AD9(-4.4,-7.6) AD10(-3.6,-7.6) AD11(-2.8,-7.6) AD12(-2,-7.6) AD13(-1.2,-7.6) AD14(-0.4,-7.6) AD15(0.4,-7.6) AD16(1.2,-7.6) AD17(2,-7.6) AD18(2.8,-7.6) AD19(3.6,-7.6) AD20(4.4,-7.6) AD21(5.2,-7.6) AD22(6,-7.6) AD23(6.8,-7.6) AD24(7.6,-7.6) AD25(8.4,-7.6) AD26(9.2,-7.6) AD27(10,-7.6) AD28(10.8,-7.6) AE1(-10.8,-8.4) AE2(-10,-8.4) AE3(-9.2,-8.4) AE5(-7.6,-8.4) AE6(-6.8,-8.4) AE7(-6,-8.4) AE8(-5.2,-8.4) AE9(-4.4,-8.4) AE10(-3.6,-8.4) AE11(-2.8,-8.4) AE12(-2,-8.4) AE13(-1.2,-8.4) AE14(-0.4,-8.4) AE15(0.4,-8.4) AE16(1.2,-8.4) AE17(2,-8.4) AE18(2.8,-8.4) AE19(3.6,-8.4) AE20(4.4,-8.4) AE21(5.2,-8.4) AE22(6,-8.4) AE23(6.8,-8.4) AE24(7.6,-8.4) AE26(9.2,-8.4) AE27(10,-8.4) AE28(10.8,-8.4) AF1(-10.8,-9.2) AF2(-10,-9.2) AF3(-9.2,-9.2) AF4(-8.4,-9.2) AF5(-7.6,-9.2) AF6(-6.8,-9.2) AF8(-5.2,-9.2) AF9(-4.4,-9.2) AF11(-2.8,-9.2) AF12(-2,-9.2) AF14(-0.4,-9.2) AF15(0.4,-9.2) AF17(2,-9.2) AF18(2.8,-9.2) AF20(4.4,-9.2) AF21(5.2,-9.2) AF22(6,-9.2) AF23(6.8,-9.2) AF24(7.6,-9.2) AF25(8.4,-9.2) AF26(9.2,-9.2) AF27(10,-9.2) AF28(10.8,-9.2) AG1(-10.8,-10) AG2(-10,-10) AG3(-9.2,-10) AG4(-8.4,-10) AG5(-7.6,-10) AG6(-6.8,-10) AG7(-6,-10) AG8(-5.2,-10) AG9(-4.4,-10) AG10(-3.6,-10) AG11(-2.8,-10) AG12(-2,-10) AG13(-1.2,-10) AG14(-0.4,-10) AG15(0.4,-10) AG16(1.2,-10) AG17(2,-10) AG18(2.8,-10) AG19(3.6,-10) AG20(4.4,-10) AG21(5.2,-10) AG22(6,-10) AG23(6.8,-10) AG24(7.6,-10) AG25(8.4,-10) AG26(9.2,-10) AG27(10,-10) AG28(10.8,-10) AH1(-10.8,-10.8) AH2(-10,-10.8) AH3(-9.2,-10.8) AH4(-8.4,-10.8) AH5(-7.6,-10.8) AH6(-6.8,-10.8) AH7(-6,-10.8) AH8(-5.2,-10.8) AH9(-4.4,-10.8) AH10(-3.6,-10.8) AH11(-2.8,-10.8) AH12(-2,-10.8) AH13(-1.2,-10.8) AH14(-0.4,-10.8) AH15(0.4,-10.8) AH16(1.2,-10.8) AH17(2,-10.8) AH18(2.8,-10.8) AH19(3.6,-10.8) AH20(4.4,-10.8) AH21(5.2,-10.8) AH22(6,-10.8) AH23(6.8,-10.8) AH24(7.6,-10.8) AH25(8.4,-10.8) AH26(9.2,-10.8) AH27(10,-10.8) AH28(10.8,-10.8) B1(-10.8,10) B2(-10,10) B3(-9.2,10) B4(-8.4,10) B5(-7.6,10) B6(-6.8,10) B7(-6,10) B8(-5.2,10) B9(-4.4,10) B10(-3.6,10) B11(-2.8,10) B12(-2,10) B13(-1.2,10) B14(-0.4,10) B15(0.4,10) B16(1.2,10) B17(2,10) B18(2.8,10) B19(3.6,10) B20(4.4,10) B21(5.2,10) B22(6,10) B23(6.8,10) B24(7.6,10) B25(8.4,10) B26(9.2,10) B27(10,10) B28(10.8,10) C1(-10.8,9.2) C2(-10,9.2) C3(-9.2,9.2) C4(-8.4,9.2) C5(-7.6,9.2) C6(-6.8,9.2) C7(-6,9.2) C8(-5.2,9.2) C9(-4.4,9.2) C11(-2.8,9.2) C12(-2,9.2) C14(-0.4,9.2) C15(0.4,9.2) C17(2,9.2) C18(2.8,9.2) C20(4.4,9.2) C21(5.2,9.2) C23(6.8,9.2) C24(7.6,9.2) C25(8.4,9.2) C26(9.2,9.2) C27(10,9.2) C28(10.8,9.2) D1(-10.8,8.4) D2(-10,8.4) D3(-9.2,8.4) D5(-7.6,8.4) D6(-6.8,8.4) D7(-6,8.4) D8(-5.2,8.4) D9(-4.4,8.4) D10(-3.6,8.4) D11(-2.8,8.4) D12(-2,8.4) D13(-1.2,8.4) D14(-0.4,8.4) D15(0.4,8.4) D16(1.2,8.4) D17(2,8.4) D18(2.8,8.4) D19(3.6,8.4) D20(4.4,8.4) D21(5.2,8.4) D22(6,8.4) D23(6.8,8.4) D24(7.6,8.4) D26(9.2,8.4) D27(10,8.4) D28(10.8,8.4) E1(-10.8,7.6) E2(-10,7.6) E3(-9.2,7.6) E4(-8.4,7.6) E5(-7.6,7.6) E6(-6.8,7.6) E7(-6,7.6) E8(-5.2,7.6) E9(-4.4,7.6) E10(-3.6,7.6) E11(-2.8,7.6) E12(-2,7.6) E13(-1.2,7.6) E14(-0.4,7.6) E15(0.4,7.6) E16(1.2,7.6) E17(2,7.6) E18(2.8,7.6) E19(3.6,7.6) E20(4.4,7.6) E21(5.2,7.6) E22(6,7.6) E23(6.8,7.6) E24(7.6,7.6) E25(8.4,7.6) E26(9.2,7.6) E27(10,7.6) E28(10.8,7.6) F1(-10.8,6.8) F2(-10,6.8) F3(-9.2,6.8) F4(-8.4,6.8) F5(-7.6,6.8) F6(-6.8,6.8) F7(-6,6.8) F8(-5.2,6.8) F9(-4.4,6.8) F10(-3.6,6.8) F11(-2.8,6.8) F12(-2,6.8) F13(-1.2,6.8) F14(-0.4,6.8) F15(0.4,6.8) F16(1.2,6.8) F17(2,6.8) F18(2.8,6.8) F19(3.6,6.8) F20(4.4,6.8) F21(5.2,6.8) F22(6,6.8) F23(6.8,6.8) F24(7.6,6.8) F25(8.4,6.8) F26(9.2,6.8) F27(10,6.8) F28(10.8,6.8) G1(-10.8,6) G2(-10,6) G4(-8.4,6) G5(-7.6,6) G6(-6.8,6) G7(-6,6) G8(-5.2,6) G9(-4.4,6) G10(-3.6,6) G11(-2.8,6) G12(-2,6) G13(-1.2,6) G14(-0.4,6) G15(0.4,6) G16(1.2,6) G17(2,6) G18(2.8,6) G19(3.6,6) G20(4.4,6) G21(5.2,6) G22(6,6) G23(6.8,6) G24(7.6,6) G25(8.4,6) G26(9.2,6) G27(10,6) G28(10.8,6) H1(-10.8,5.2) H2(-10,5.2) H3(-9.2,5.2) H4(-8.4,5.2) H5(-7.6,5.2) H6(-6.8,5.2) H7(-6,5.2) H8(-5.2,5.2) H9(-4.4,5.2) H10(-3.6,5.2) H11(-2.8,5.2) H12(-2,5.2) H13(-1.2,5.2) H14(-0.4,5.2) H15(0.4,5.2) H16(1.2,5.2) H17(2,5.2) H18(2.8,5.2) H19(3.6,5.2) H20(4.4,5.2) H21(5.2,5.2) H22(6,5.2) H23(6.8,5.2) H24(7.6,5.2) H25(8.4,5.2) H26(9.2,5.2) H27(10,5.2) H28(10.8,5.2) J1(-10.8,4.4) J2(-10,4.4) J3(-9.2,4.4) J4(-8.4,4.4) J5(-7.6,4.4) J6(-6.8,4.4) J7(-6,4.4) J8(-5.2,4.4) J9(-4.4,4.4) J10(-3.6,4.4) J11(-2.8,4.4) J12(-2,4.4) J13(-1.2,4.4) J14(-0.4,4.4) J15(0.4,4.4) J16(1.2,4.4) J17(2,4.4) J18(2.8,4.4) J19(3.6,4.4) J20(4.4,4.4) J21(5.2,4.4) J22(6,4.4) J23(6.8,4.4) J24(7.6,4.4) J25(8.4,4.4) J26(9.2,4.4) J27(10,4.4) J28(10.8,4.4) K1(-10.8,3.6) K2(-10,3.6) K4(-8.4,3.6) K5(-7.6,3.6) K6(-6.8,3.6) K7(-6,3.6) K8(-5.2,3.6) K9(-4.4,3.6) K10(-3.6,3.6) K11(-2.8,3.6) K12(-2,3.6) K13(-1.2,3.6) K14(-0.4,3.6) K15(0.4,3.6) K16(1.2,3.6) K17(2,3.6) K18(2.8,3.6) K19(3.6,3.6) K20(4.4,3.6) K21(5.2,3.6) K22(6,3.6) K23(6.8,3.6) K24(7.6,3.6) K25(8.4,3.6) K27(10,3.6) K28(10.8,3.6) L1(-10.8,2.8) L2(-10,2.8) L3(-9.2,2.8) L4(-8.4,2.8) L5(-7.6,2.8) L6(-6.8,2.8) L7(-6,2.8) L8(-5.2,2.8) L9(-4.4,2.8) L10(-3.6,2.8) L11(-2.8,2.8) L12(-2,2.8) L13(-1.2,2.8) L14(-0.4,2.8) L15(0.4,2.8) L16(1.2,2.8) L17(2,2.8) L18(2.8,2.8) L19(3.6,2.8) L20(4.4,2.8) L21(5.2,2.8) L22(6,2.8) L23(6.8,2.8) L24(7.6,2.8) L25(8.4,2.8) L26(9.2,2.8) L27(10,2.8) L28(10.8,2.8) M1(-10.8,2) M2(-10,2) M3(-9.2,2) M4(-8.4,2) M5(-7.6,2) M6(-6.8,2) M7(-6,2) M8(-5.2,2) M9(-4.4,2) M10(-3.6,2) M11(-2.8,2) M12(-2,2) M13(-1.2,2) M14(-0.4,2) M15(0.4,2) M16(1.2,2) M17(2,2) M18(2.8,2) M19(3.6,2) M20(4.4,2) M21(5.2,2) M22(6,2) M23(6.8,2) M24(7.6,2) M25(8.4,2) M26(9.2,2) M27(10,2) M28(10.8,2) N1(-10.8,1.2) N2(-10,1.2) N4(-8.4,1.2) N5(-7.6,1.2) N6(-6.8,1.2) N7(-6,1.2) N8(-5.2,1.2) N9(-4.4,1.2) N10(-3.6,1.2) N11(-2.8,1.2) N12(-2,1.2) N13(-1.2,1.2) N14(-0.4,1.2) N15(0.4,1.2) N16(1.2,1.2) N17(2,1.2) N18(2.8,1.2) N19(3.6,1.2) N20(4.4,1.2) N21(5.2,1.2) N22(6,1.2) N23(6.8,1.2) N24(7.6,1.2) N25(8.4,1.2) N27(10,1.2) N28(10.8,1.2) P1(-10.8,0.4) P2(-10,0.4) P3(-9.2,0.4) P4(-8.4,0.4) P5(-7.6,0.4) P6(-6.8,0.4) P7(-6,0.4) P8(-5.2,0.4) P9(-4.4,0.4) P10(-3.6,0.4) P11(-2.8,0.4) P12(-2,0.4) P13(-1.2,0.4) P14(-0.4,0.4) P15(0.4,0.4) P16(1.2,0.4) P17(2,0.4) P18(2.8,0.4) P19(3.6,0.4) P20(4.4,0.4) P21(5.2,0.4) P22(6,0.4) P23(6.8,0.4) P24(7.6,0.4) P25(8.4,0.4) P26(9.2,0.4) P27(10,0.4) P28(10.8,0.4) R1(-10.8,-0.4) R2(-10,-0.4) R3(-9.2,-0.4) R4(-8.4,-0.4) R5(-7.6,-0.4) R6(-6.8,-0.4) R7(-6,-0.4) R8(-5.2,-0.4) R9(-4.4,-0.4) R10(-3.6,-0.4) R11(-2.8,-0.4) R12(-2,-0.4) R13(-1.2,-0.4) R14(-0.4,-0.4) R15(0.4,-0.4) R16(1.2,-0.4) R17(2,-0.4) R18(2.8,-0.4) R19(3.6,-0.4) R20(4.4,-0.4) R21(5.2,-0.4) R22(6,-0.4) R23(6.8,-0.4) R24(7.6,-0.4) R25(8.4,-0.4) R26(9.2,-0.4) R27(10,-0.4) R28(10.8,-0.4) T1(-10.8,-1.2) T2(-10,-1.2) T4(-8.4,-1.2) T5(-7.6,-1.2) T6(-6.8,-1.2) T7(-6,-1.2) T8(-5.2,-1.2) T9(-4.4,-1.2) T10(-3.6,-1.2) T11(-2.8,-1.2) T12(-2,-1.2) T13(-1.2,-1.2) T14(-0.4,-1.2) T15(0.4,-1.2) T16(1.2,-1.2) T17(2,-1.2) T18(2.8,-1.2) T19(3.6,-1.2) T20(4.4,-1.2) T21(5.2,-1.2) T22(6,-1.2) T23(6.8,-1.2) T24(7.6,-1.2) T25(8.4,-1.2) T27(10,-1.2) T28(10.8,-1.2) U1(-10.8,-2) U2(-10,-2) U3(-9.2,-2) U4(-8.4,-2) U5(-7.6,-2) U6(-6.8,-2) U7(-6,-2) U8(-5.2,-2) U9(-4.4,-2) U10(-3.6,-2) U11(-2.8,-2) U12(-2,-2) U13(-1.2,-2) U14(-0.4,-2) U15(0.4,-2) U16(1.2,-2) U17(2,-2) U18(2.8,-2) U19(3.6,-2) U20(4.4,-2) U21(5.2,-2) U22(6,-2) U23(6.8,-2) U24(7.6,-2) U25(8.4,-2) U26(9.2,-2) U27(10,-2) U28(10.8,-2) V1(-10.8,-2.8) V2(-10,-2.8) V3(-9.2,-2.8) V4(-8.4,-2.8) V5(-7.6,-2.8) V6(-6.8,-2.8) V7(-6,-2.8) V8(-5.2,-2.8) V9(-4.4,-2.8) V10(-3.6,-2.8) V11(-2.8,-2.8) V12(-2,-2.8) V13(-1.2,-2.8) V14(-0.4,-2.8) V15(0.4,-2.8) V16(1.2,-2.8) V17(2,-2.8) V18(2.8,-2.8) V19(3.6,-2.8) V20(4.4,-2.8) V21(5.2,-2.8) V22(6,-2.8) V23(6.8,-2.8) V24(7.6,-2.8) V25(8.4,-2.8) V26(9.2,-2.8) V27(10,-2.8) V28(10.8,-2.8) W1(-10.8,-3.6) W2(-10,-3.6) W4(-8.4,-3.6) W5(-7.6,-3.6) W6(-6.8,-3.6) W7(-6,-3.6) W8(-5.2,-3.6) W9(-4.4,-3.6) W10(-3.6,-3.6) W11(-2.8,-3.6) W12(-2,-3.6) W13(-1.2,-3.6) W14(-0.4,-3.6) W15(0.4,-3.6) W16(1.2,-3.6) W17(2,-3.6) W18(2.8,-3.6) W19(3.6,-3.6) W20(4.4,-3.6) W21(5.2,-3.6) W22(6,-3.6) W23(6.8,-3.6) W24(7.6,-3.6) W25(8.4,-3.6) W27(10,-3.6) W28(10.8,-3.6) Y1(-10.8,-4.4) Y2(-10,-4.4) Y3(-9.2,-4.4) Y4(-8.4,-4.4) Y5(-7.6,-4.4) Y6(-6.8,-4.4) Y7(-6,-4.4) Y8(-5.2,-4.4) Y9(-4.4,-4.4) Y10(-3.6,-4.4) Y11(-2.8,-4.4) Y12(-2,-4.4) Y13(-1.2,-4.4) Y14(-0.4,-4.4) Y15(0.4,-4.4) Y16(1.2,-4.4) Y17(2,-4.4) Y18(2.8,-4.4) Y19(3.6,-4.4) Y20(4.4,-4.4) Y21(5.2,-4.4) Y22(6,-4.4) Y23(6.8,-4.4) Y24(7.6,-4.4) Y25(8.4,-4.4) Y26(9.2,-4.4) Y27(10,-4.4) Y28(10.8,-4.4)
BGA96C80P9X16_800X1400X120
  round 0.4 smd: A1(-3.2,6) A2(-2.4,6) A3(-1.6,6) A7(1.6,6) A8(2.4,6) A9(3.2,6) B1(-3.2,5.2) B2(-2.4,5.2) B3(-1.6,5.2) B7(1.6,5.2) B8(2.4,5.2) B9(3.2,5.2) C1(-3.2,4.4) C2(-2.4,4.4) C3(-1.6,4.4) C7(1.6,4.4) C8(2.4,4.4) C9(3.2,4.4) D1(-3.2,3.6) D2(-2.4,3.6) D3(-1.6,3.6) D7(1.6,3.6) D8(2.4,3.6) D9(3.2,3.6) E1(-3.2,2.8) E2(-2.4,2.8) E3(-1.6,2.8) E7(1.6,2.8) E8(2.4,2.8) E9(3.2,2.8) F1(-3.2,2) F2(-2.4,2) F3(-1.6,2) F7(1.6,2) F8(2.4,2) F9(3.2,2) G1(-3.2,1.2) G2(-2.4,1.2) G3(-1.6,1.2) G7(1.6,1.2) G8(2.4,1.2) G9(3.2,1.2) H1(-3.2,0.4) H2(-2.4,0.4) H3(-1.6,0.4) H7(1.6,0.4) H8(2.4,0.4) H9(3.2,0.4) J1(-3.2,-0.4) J2(-2.4,-0.4) J3(-1.6,-0.4) J7(1.6,-0.4) J8(2.4,-0.4) J9(3.2,-0.4) K1(-3.2,-1.2) K2(-2.4,-1.2) K3(-1.6,-1.2) K7(1.6,-1.2) K8(2.4,-1.2) K9(3.2,-1.2) L1(-3.2,-2) L2(-2.4,-2) L3(-1.6,-2) L7(1.6,-2) L8(2.4,-2) L9(3.2,-2) M1(-3.2,-2.8) M2(-2.4,-2.8) M3(-1.6,-2.8) M7(1.6,-2.8) M8(2.4,-2.8) M9(3.2,-2.8) N1(-3.2,-3.6) N2(-2.4,-3.6) N3(-1.6,-3.6) N7(1.6,-3.6) N8(2.4,-3.6) N9(3.2,-3.6) P1(-3.2,-4.4) P2(-2.4,-4.4) P3(-1.6,-4.4) P7(1.6,-4.4) P8(2.4,-4.4) P9(3.2,-4.4) R1(-3.2,-5.2) R2(-2.4,-5.2) R3(-1.6,-5.2) R7(1.6,-5.2) R8(2.4,-5.2) R9(3.2,-5.2) T1(-3.2,-6) T2(-2.4,-6) T3(-1.6,-6) T7(1.6,-6) T8(2.4,-6) T9(3.2,-6)
